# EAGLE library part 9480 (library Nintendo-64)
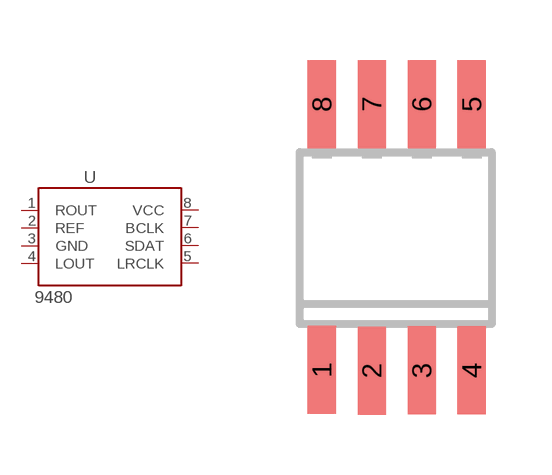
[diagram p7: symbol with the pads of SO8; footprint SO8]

Designator prefix -

## 9480  [SO8]
1  ROUT  out
2  REF  pwr
3  GND  out
4  LOUT  pwr
5  LRCLK  out
6  SDAT  in
7  BCLK  in
8  VCC  out

## Footprint SO8 (pad centres in mm)
smd 0.7 x 2.2: 1 -1.85,-3.795; 2 -0.6,-3.815; 3 0.65,-3.81; 4 1.9,-3.805; 5 1.9,2.85; 6 0.65,2.85; 7 -0.6,2.85; 8 -1.85,2.85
